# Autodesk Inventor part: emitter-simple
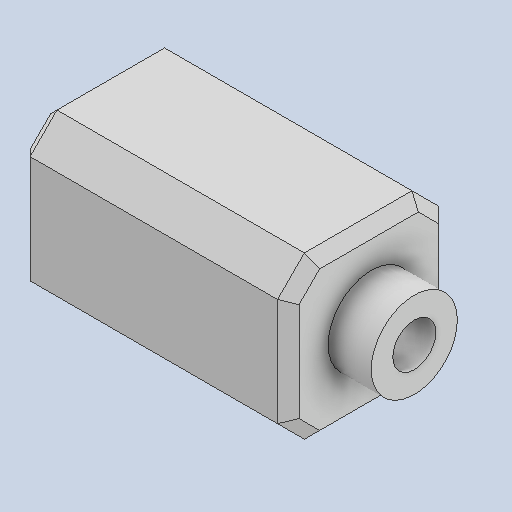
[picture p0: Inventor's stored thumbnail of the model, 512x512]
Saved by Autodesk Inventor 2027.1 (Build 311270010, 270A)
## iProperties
Created: 2026-07
Part Number: emitter-simple
Material: Generic
Document SubType Name: Modeling
Designer: dunge
Density: 1 g/cm^3
Appearance: Default
Author: dunge
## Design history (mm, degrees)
sketch "Sketch1"
  geometry: L1 (16.089, 9.798)-(-15.661, 9.798); L2 (-15.661, 9.798)-(-15.661, -9.252); L3 (-15.661, -9.252)-(16.089, -9.252); L4 (16.089, -9.252)-(16.089, 9.798); 1 further point
  constraints: 8 end point, 2 parallel, 1 horizontal, 1 perpendicular
  dimensions: "d0" = 19.05 distance of L3.end L1.start; "d1" = 31.75 distance of L1.start L1.end
extrude "Extrusion1" new body sketch "Sketch1" distance "d2" = 19.05; taper "d3" = 0 deg
sketch "Sketch2"
  geometry: C1 r 5.08 at (9.798, 9.516); 1 further point
  constraints: 1 centre point
  dimensions: "d4" = 10.16 diameter of C1
extrude "Extrusion2" join sketch "Sketch2" distance "d5" = 5.08; taper "d6" = 0 deg
chamfer "Chamfer1" distance "d7" = 3.175; stored, may be unused: second distance "d8" = 3.175, angle "d9" = 45 deg
sketch "Sketch3"
  geometry: C1 r 2.54 at (0, 0); 1 further point
  constraints: 1 centre point
  dimensions: "d10" = 5.08 diameter of C1
extrude "Extrusion3" cut sketch "Sketch3" distance "d11" = 16.1925; taper "d12" = 0 deg
chamfer "Chamfer2" distance "d13" = 1.27; stored, may be unused: second distance "d14" = 3.175, angle "d15" = 45 deg
body "Solid1"
